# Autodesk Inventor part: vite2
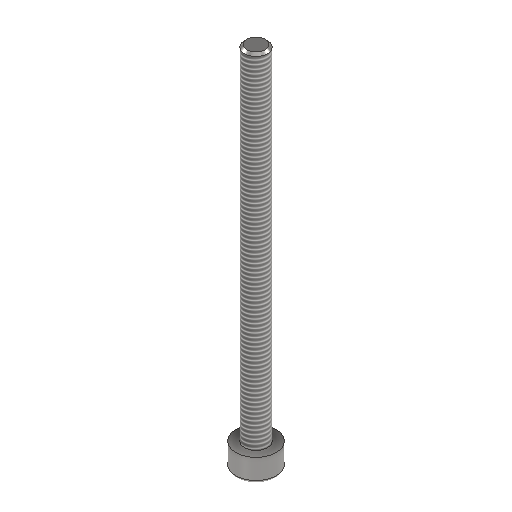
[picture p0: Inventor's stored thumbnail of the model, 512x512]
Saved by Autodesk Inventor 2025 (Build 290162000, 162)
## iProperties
Created: 2025-05
Part Number: vite2
Material: Acciaio inossidabile
Document SubType Name: Modeling
Designer: R5800u
Density: 8 g/cm^3
Appearance: Semilucidato
Author: R5800u
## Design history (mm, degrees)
sketch "Schizzo1"
  geometry: L1 (0, 0)-(3.5, 0); L2 (3.5, 0)-(3.5, 4); L3 (3.5, 4)-(2, 4); L4 (2, 4)-(2, 64); L5 (2, 64)-(0, 64); L6 (0, 64)-(0, 0)
  constraints: 12 end point, 4 perpendicular, 2 horizontal
  dimensions: "d0" = 3.5 distance of L1.start L1.end; "d1" = 4 distance of L1.end L2.end; "d3" = 60 distance of L3.end L4.end; "d4" = 2 distance between parallel lines of L4 L6
revolve "Rivoluzione1" sketch "Schizzo1" stored, may be unused: angle "d5" = 90 deg
sketch "Schizzo2"
  geometry: L1 (0, -1.5)-(-1.299, -0.75); L2 (-1.299, -0.75)-(-1.299, 0.75); L3 (-1.299, 0.75)-(0, 1.5); L4 (0, 1.5)-(1.299, 0.75); L5 (1.299, 0.75)-(1.299, -0.75); L6 (1.299, -0.75)-(0, -1.5); C1 r 3.5 at (0, 0) reference; 2 further points
  constraints: 12 end point, 1 coincident, 13 other
  dimensions: "d14" = 1.5 distance of L4.end L5.end
extrude "Estrusione1" cut sketch "Schizzo2" distance "d6" = 2; taper "d7" = 0 deg
chamfer "Smusso1" distance "d8" = 0.4; stored, may be unused: second distance "d9" = 2, angle "d10" = 45 deg
feature "Filettatura1" dims "d11" = 59.6, "d12" = 0
fillet "Raccordo1" dims "d13" = 0.5
node "Solido1"
